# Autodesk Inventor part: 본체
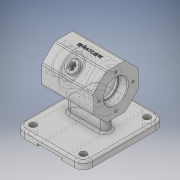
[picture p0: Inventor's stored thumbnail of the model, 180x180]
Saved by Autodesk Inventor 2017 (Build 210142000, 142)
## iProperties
Part Number: 본체
Material: 일반
Document SubType Name: Modeling
Designer: Administrator
Density: 1 g/cm^3
Appearance: 기본값
Author: Administrator
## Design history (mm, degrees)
sketch "스케치1"
  geometry: L1 (46, 55)-(-46, 55); L2 (-46, 55)-(-46, -55); L3 (-46, -55)-(46, -55); L4 (46, -55)-(46, 55); L5 (46, 55)-(-46, -55); L6 (-46, 55)-(46, -55); 1 further point
  constraints: 12 end point, 2 midpoint, 2 parallel, 1 horizontal, 1 perpendicular
  dimensions: "d0" = 92 distance of L2.end L3.end; "d1" = 110 distance of L1.end L2.end
extrude "돌출1" new body sketch "스케치1" distance "d2" = 10; taper "d3" = 0 deg
sketch "스케치2"
  geometry: L1 (92, 12.426)-(92, -12.426); L2 (92, -12.426)-(74.426, -30); L3 (74.426, -30)-(49.574, -30); L4 (49.574, -30)-(32, -12.426); L5 (32, -12.426)-(32, 12.426); L6 (32, 12.426)-(49.574, 30); L7 (49.574, 30)-(74.426, 30); L8 (74.426, 30)-(92, 12.426); C1 r 30 at (62, 0); 2 further points
  constraints: 16 end point, 1 centre point, 1 coincident, 1 horizontal alignment, 17 other
  dimensions: "d6" = 60 distance between parallel lines of L6 L2; "d7" = 60 diameter of C1; "d8" = 62 distance of point (62, 0) point (0, 0); "d10" = 92 distance from line of point (0, 0) L1
extrude "돌출2" join sketch "스케치2" stored distance "d11" = 70; taper "d12" = 0 deg
sketch "스케치3"
  geometry: L1 (-20, 0)-(20, 0); L2 (-20, -6)-(20, -6); L3 (20, 6)-(-20, 6); A1 r 6 centre (-20, 0) between (-20, 6) and (-20, -6); A2 r 6 centre (20, 0) between (20, -6) and (20, 6); 2 further points
  constraints: 8 end point, 4 point on circle, 4 tangent, 2 centre point, 2 coincident, 1 horizontal, 1 midpoint, 1 parallel
  dimensions: "d13" = 12 distance between parallel lines of L2 L3; "d14" = 40 distance of L1.end L1.start
extrude "돌출3" join sketch "스케치3" distance "d15" = 70; taper "d16" = 0 deg
sketch "스케치4"
  geometry: L1 (30, 0)-(62, 0); L2 (62, 0)-(62, 3); L3 (62, 3)-(30, 3); L4 (30, 3)-(30, 0); L5 (0, 0)-(92, 0) reference; 5 further points
  constraints: 8 end point, 4 midpoint, 2 parallel, 1 coincident, 1 horizontal, 1 perpendicular, 1 vertical alignment
  dimensions: "d17" = 32 distance of L2.end L3.end; "d18" = 3 distance of L1.end L2.end
extrude "돌출4" cut sketch "스케치4" stored distance "d19" = 70; taper "d20" = 0 deg
fillet "모깎기1" dims "d21" = 12
sketch "스케치5"
  geometry: A1 r 12 centre (-34, 43) between (-34, 55) and (-46, 43) reference; A2 r 12 centre (34, 43) between (46, 43) and (34, 55) reference; A3 r 12 centre (34, -43) between (34, -55) and (46, -43) reference; A4 r 12 centre (-34, -43) between (-46, -43) and (-34, -55) reference; 5 further points
  constraints: 4 coincident
hole "구멍1" sketch "스케치5" at (-34, 43), (34, 43), (34, -43), (-34, -43) diameter "d22" = 9; stored, may be unused: countersink angle "d26" = 90 deg, drill point angle "d28" = 118 deg; dims "d23" = 6, "d24" = 4, "d25" = 2, "d27" = 15
sketch "스케치6"
  geometry: L1 (49.574, -30)-(74.426, -30) reference; L2 (62, -30)-(62, 30); L3 (74.426, 30)-(49.574, 30) reference; L4 (74.426, -30)-(92, -12.426) reference; L5 (62, 0)-(86.749, 24.749); L6 (86.749, 24.749)-(92.406, 19.092); L7 (92.406, 19.092)-(67.657, -5.657); L8 (67.657, -5.657)-(62, 0); L9 (92, 12.426)-(74.426, 30) reference; 2 further points
  constraints: 10 end point, 4 midpoint, 2 parallel, 1 perpendicular, 1 point on line
  dimensions: "d35" = 5 distance between parallel lines of L9 L6; "d36" = 16 diameter of L7 L5
revolve "회전1" sketch "스케치6" stored, may be unused: angle "d37" = 90 deg
sketch "스케치7"
  geometry: L1 (-35, 74.426)-(-35, 49.574) reference; L2 (35, 49.574)-(35, 74.426) reference; L3 (-35, 62)-(35, 62); L4 (-35, 62)-(-35, 78); L5 (-35, 92)-(-35, 74.426) reference; L6 (-35, 78)-(-23, 78); L7 (-23, 78)-(-23, 76); L8 (-23, 76)-(-20, 76); L9 (-20, 76)-(-20, 87); L10 (-20, 87)-(20, 87); L11 (20, 87)-(20, 76); L12 (20, 76)-(23, 76); L13 (23, 76)-(23, 78); L14 (23, 78)-(35, 78); L15 (35, 78)-(35, 62); L16 (35, 74.426)-(-35, 74.426) reference; 1 further point
  constraints: 24 end point, 7 perpendicular, 5 point on line, 2 midpoint, 1 horizontal
  dimensions: "d38" = 32 diameter of L6 L3; "d39" = 50 diameter of L10 L3; "d40" = 28 diameter of L8 L3; "d41" = 12 distance of L4.end L6.end; "d42" = 40 distance of L9.end L10.end; "d43" = 12 distance of L13.end L14.end; "d44" = 3 distance of L7.end L8.end
revolve "회전2" sketch "스케치7" stored, may be unused: angle "d45" = 90 deg
sketch "스케치8"
  geometry: C1 r 14 at (0, 62) reference; A1 r 23 centre (0, 62) between (0, 85) and (-23, 62); 3 further points
  constraints: 4 point on circle, 2 horizontal alignment, 2 vertical alignment, 1 centre point, 1 coincident
  dimensions: "d46" = 46 diameter of A1
hole "구멍2" sketch "스케치8" at (0, 85), (-23, 62), (23, 62), (0, 39) diameter "d47" = 3.242; stored, may be unused: countersink angle "d51" = 90 deg, drill point angle "d53" = 118 deg; dims "d48" = 8, "d49" = 4, "d50" = 2, "d52" = 10
node "작업 평면1"
fillet "모깎기2" dims "d54" = 0.3
chamfer "모따기1" distance "d55" = 1; stored, may be unused: second distance "d56" = 2, angle "d57" = 45 deg
fillet "모깎기3" dims "d58" = 3
fillet "모깎기4" dims "d59" = 3
sketch "스케치9"
  geometry: C1 r 8 at (0, 0) reference; 2 further points
  constraints: 1 coincident
hole "구멍3" sketch "스케치9" at (0, 0) diameter "d60" = 8; stored, may be unused: countersink angle "d64" = 90 deg, drill point angle "d66" = 118 deg; dims "d61" = 8, "d62" = 4, "d63" = 2, "d65" = 15
fillet "모깎기5" dims "d67" = 1
fillet "모깎기6" dims "d68" = 1
fillet "모깎기7" dims "d69" = 3
node "작업 평면2"
sketch "스케치10"
  geometry: L1 (0, 0)-(70, 0) reference; L2 (70, 18.816)-(0, 18.816) reference; L3 (0, 2.121)-(0, 17.938) reference; 2 further points
  constraints: 1 other
  dimensions: "d72" = 30 distance from line of point (35, -11.184) L2; "d73" = 35 distance from line of point (35, -11.184) L3
feature "엠보싱1" sketch "스케치10" dims "d0" = 92, "d1" = 110, "d74" = 0.5, "d75" = 0
fillet "모깎기8" dims "d76" = 3
node "솔리드1"
mirror "미러1"
other parameters: "d70" = 22
